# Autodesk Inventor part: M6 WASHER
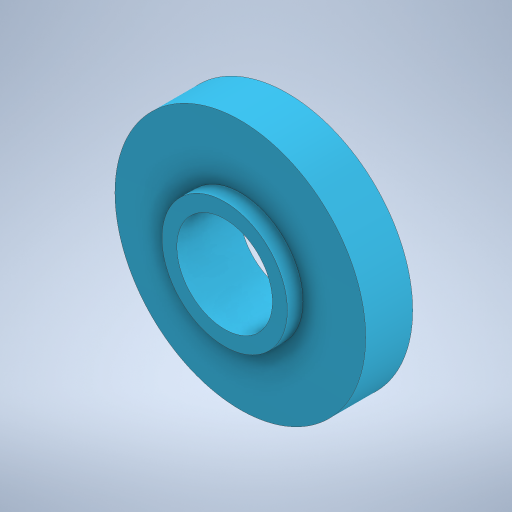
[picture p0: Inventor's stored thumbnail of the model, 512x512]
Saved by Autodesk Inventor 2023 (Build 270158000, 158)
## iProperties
Created: 2025-07
Part Number: M6 WASHER
Material: Generic
Document SubType Name: Modeling
Designer: erjon
Density: 1 g/cm^3
Appearance: Default
Author: erjon
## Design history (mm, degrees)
feature "Base1"
body "Solid1"
